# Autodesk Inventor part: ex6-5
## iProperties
Author: Elise Moss
Created: 2001-09
Part Number: ex6-5
Document SubType Name: Modeling
Designer: Elise Moss
Control State: 0
Master: False
Checked Out: False
PropertySet Name: Design Tracking Control
Shininess: 64.0
Angle Display Precision: 2
Document Length Units: 11272
Document Angle Units: 11286
Document Time Units: 11279
Document Mass Units: 11290
Document Length Units Precision: 3
Document Angle Units Precision: 2
Compacted: True
PropertySet Name: _Private Model Information
Density: 0.0
Volumn: 0.0
Area: 0.0
PropertySet Name: Model Information
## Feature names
1. Extrusion1
